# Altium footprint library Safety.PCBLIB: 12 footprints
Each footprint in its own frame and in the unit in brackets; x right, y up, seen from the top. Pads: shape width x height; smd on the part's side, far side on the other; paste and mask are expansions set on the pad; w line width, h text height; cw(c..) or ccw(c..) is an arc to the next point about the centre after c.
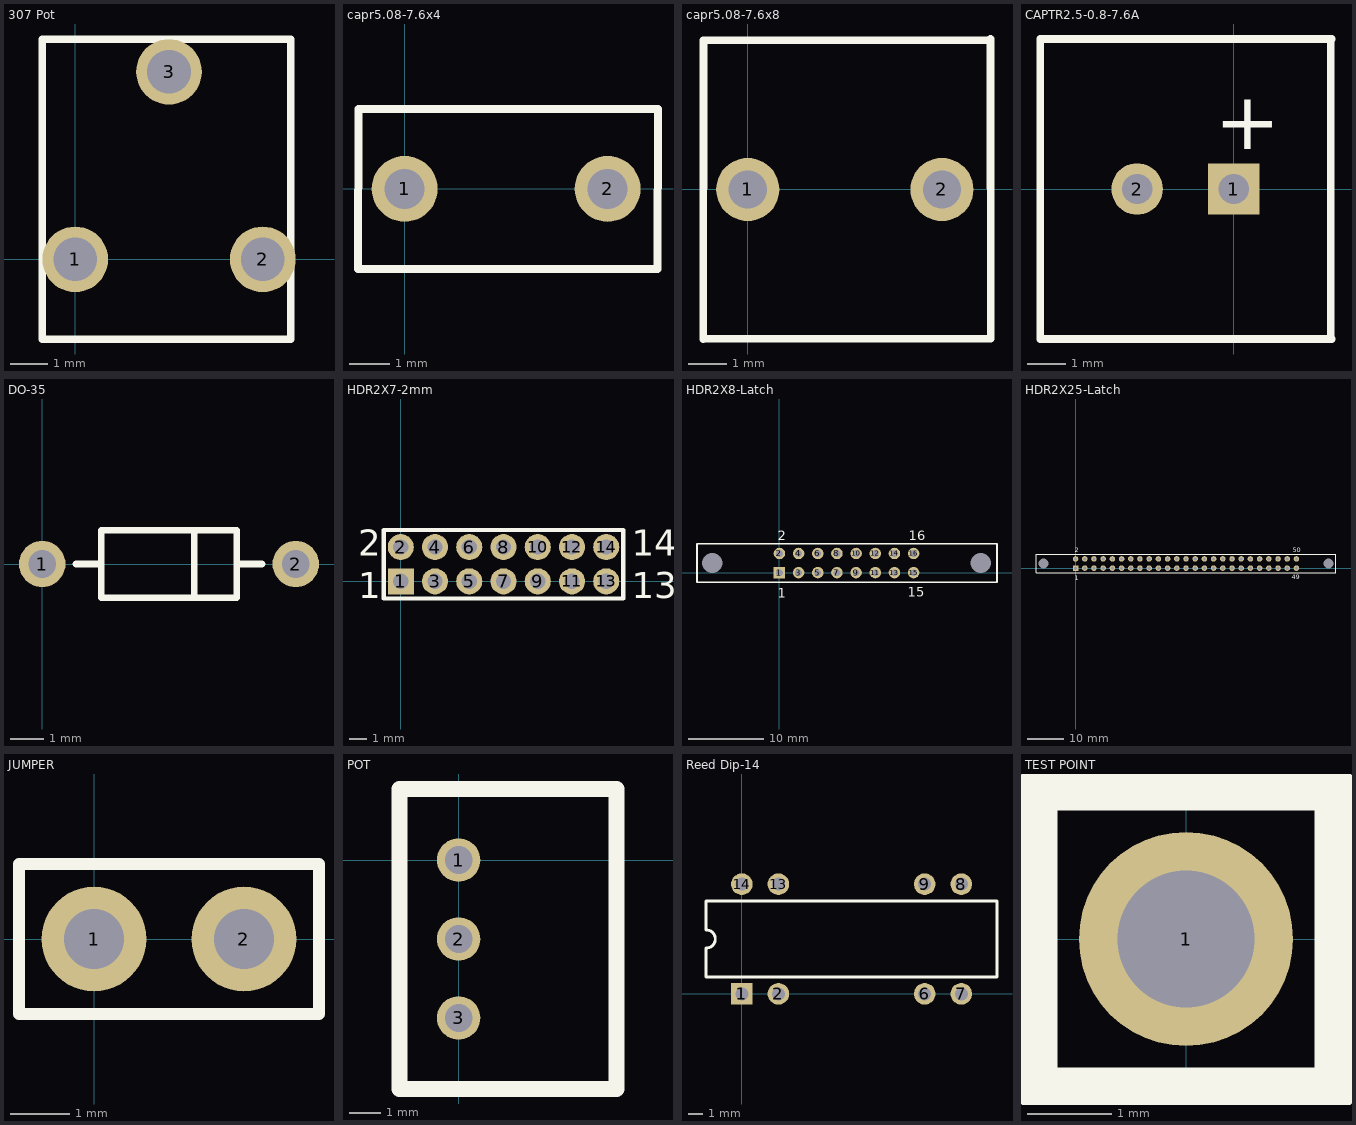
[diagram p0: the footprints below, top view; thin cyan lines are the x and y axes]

## 307 Pot [mil]
height 300
pads (3):
  round 70 hole 46.5: 1(0,0) 2(200,0) 3(100,200)
Top Overlay:
  lines w8: -35,-85 230,-85 230,235 -35,235 -35,-85

## capr5.08-7.6x4 [mm]
height 5.004
pads (2):
  round 1.65 hole 1: 1(0,0) 2(5.08,0)
Top Overlay:
  lines w0.2: 6.3,-2 -1.168,-2.007 -1.16,2 6.34,2 6.325,-2.007

## capr5.08-7.6x8 [mm]
height 10.998
pads (2):
  round 1.65 hole 1: 1(0,0) 2(5.08,0)
Top Overlay:
  lines w0.2: 6.3,-3.905 -1.168,-3.912 -1.16,3.905 6.34,3.905 ; 6.35,3.937 6.36,-3.905

## CAPTR2.5-0.8-7.6A [mm]
height 9.906
pads (2):
  rect 1.35x1.35 hole 0.8: 1(0,0)
  round 1.35 hole 0.8: 2(-2.54,0)
Top Overlay:
  lines w0.2: 2.54,-3.937 2.54,3.937 ; 2.563,-3.937 -5.08,-3.937 -5.08,3.937 2.563,3.937
  text "+" at -0.504,1.037 h1.5

## DO-35 [mil]
height 80
pads (2):
  round 55 hole 33: 1(0,0) 2(300,0)
Top Overlay:
  lines w7.87: 40,0 70,0 ; 180,-40 180,40 ; 230,0 260,0 ; 70,-40 70,40 230,40 230,-40 70,-40

## HDR2X7-2mm [mil]
height 256
pads (14):
  rect 60x60 hole 35: 1(0,0)
  round 60 hole 35: 2(0,78.74) 3(78.74,0) 4(78.74,78.74) 5(157.48,0) 6(157.48,78.74) 7(236.22,0) 8(236.22,78.74) 9(314.96,0) 10(314.96,78.74) 11(393.7,0) 12(393.7,78.74) 13(472.44,0) 14(472.44,78.74)
Top Overlay:
  lines w10: -39.37,-39.37 -39.37,118.11 511.81,118.11 511.81,-39.37 -39.37,-39.37
  text "14" at 531.5,59.06 h60
  text "13" at 531.5,-39.37 h60
  text "2" at -98.43,59.06 h60
  text "1" at -98.43,-39.37 h60

## HDR2X8-Latch [mil]
height 1075
pads (18):
  round 0 hole 106.5: 0(-350,50) 0(1050,50)
  rect 60x60 hole 35: 1(0,0)
  round 60 hole 35: 2(0,100) 3(100,0) 4(100,100) 5(200,0) 6(200,100) 7(300,0) 8(300,100) 9(400,0) 10(400,100) 11(500,0) 12(500,100) 13(600,0) 14(600,100) 15(700,0) 16(700,100)
Top Overlay:
  lines w7.87: -430,-50 1135,-50 1135,150 -430,150 -430,-50
  text "16" at 675,170 h50
  text "15" at 670,-125 h50
  text "1" at -10,-130 h50
  text "2" at -10,170 h50

## HDR2X25-Latch [mil]
height 1075
pads (52):
  round 0 hole 106.5: 0(-350,50) 0(2750,50)
  rect 60x60 hole 35: 1(0,0)
  round 60 hole 35: 2(0,100) 3(100,0) 4(100,100) 5(200,0) 6(200,100) 7(300,0) 8(300,100) 9(400,0) 10(400,100) 11(500,0) 12(500,100) 13(600,0) 14(600,100) 15(700,0) 16(700,100) 17(800,0) 18(800,100) 19(900,0) 20(900,100) 21(1000,0) 22(1000,100) 23(1100,0) 24(1100,100) 25(1200,0) 26(1200,100) 27(1300,0) 28(1300,100) 29(1400,0) 30(1400,100) 31(1500,0) 32(1500,100) 33(1600,0) 34(1600,100) 35(1700,0) 36(1700,100) 37(1800,0) 38(1800,100) 39(1900,0) 40(1900,100) 41(2000,0) 42(2000,100) 43(2100,0) 44(2100,100) 45(2200,0) 46(2200,100) 47(2300,0) 48(2300,100) 49(2400,0) 50(2400,100)
Top Overlay:
  lines w7.87: -430,-50 2830,-50 2830,150 -430,150 -430,-50
  text "49" at 2350,-120 h50
  text "50" at 2360,170 h50
  text "1" at -10,-130 h50
  text "2" at -10,170 h50

## JUMPER [mil]
height 150
pads (2):
  round 70 hole 40: 1(0,0) 2(100,0)
Top Overlay:
  lines w8: -50,-50 150,-50 150,50 -50,50 -50,-50

## POT [mil]
height 395
pads (3):
  round 55 hole 35: 1(0,0) 2(0,-100) 3(0,-200)
Top Overlay:
  lines w20: -75,-290 200,-290 200,90 -75,90 -75,-290

## Reed Dip-14 [mm]
height 6.985
pads (8):
  rect 1.5x1.5 hole 0.9: 1(0,0)
  round 1.5 hole 0.9: 2(2.54,0) 6(12.7,0) 7(15.24,0) 8(15.24,7.62) 9(12.7,7.62) 13(2.54,7.62) 14(0,7.62)
Top Overlay:
  lines w0.2: -2.48,1.16 -2.48,3.175 ccw(c-2.48,3.81) -2.48,4.445 -2.48,6.46 17.72,6.46 17.72,1.16 -2.48,1.16

## TEST POINT [mil]
height 320
pads (1):
  round 100 hole 64: 1(0,0)
Top Overlay:
  lines w20: -70,-70 50,-70 70,-70 70,-50 70,70 -70,70 -70,-70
